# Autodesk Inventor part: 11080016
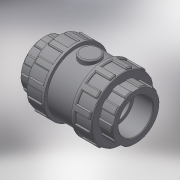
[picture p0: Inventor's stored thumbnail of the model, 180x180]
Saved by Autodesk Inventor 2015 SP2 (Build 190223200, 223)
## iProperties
Created: 2017-11
Part Number: 11080016
Material: Generic
Description: PLASSON CHECK VALVE CEM 16 PTFE COATED SPRING + EPDM O-RING
Document SubType Name: Modeling
Designer: KIM
Density: 1 g/cm^3
Appearance: Default
Author: KIM
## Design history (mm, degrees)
derived "110800 - 110600 110900-110000.ipt"
feature "Solid1::110800 - 110600 110900-110000.ipt"
tag "TaggingFeature1"
body "Solid1"
other parameters: "d0" = 71, "d1" = 16, "d2" = 45, "d3" = 14, "d4" = 12.8, "d5" = 9.8, "d7" = 22.4, "d8" = 40.5, "d13" = 0.48, "d23" = 14, "d24" = 43.2, "d25" = 0.32, "d26" = 0.48, "d27" = 6.75, "d28" = 3.375, "d29" = 10.5, "d30" = 0, "d35" = 0.48, "d39" = 22.5, "d45" = 360 deg, "d47" = 0.32, "d50" = 22.5, "d51" = 13.5, "d53" = 0, "d54" = 0.9, "d55" = 3.2, "d56" = 1.6, "d57" = 9.8, "d58" = 0, "d59" = 0.48, "d61" = 360 deg, "d_" = 16, "l_" = 14, "H_" = 71, "K_" = 45
